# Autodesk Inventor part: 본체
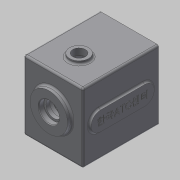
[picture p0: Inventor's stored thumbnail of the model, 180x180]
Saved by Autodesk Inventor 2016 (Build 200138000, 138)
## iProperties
Created: 2016-02
Part Number: 본체
Material: 일반
Document SubType Name: Modeling
Designer: mduedu
Density: 2.71 g/cm^3
Appearance: 기본값
Author: mduedu
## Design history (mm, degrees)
sketch "스케치1"
  geometry: L1 (-47, -47)-(47, -47); L2 (47, -47)-(47, 63); L3 (47, 63)-(-47, 63); L4 (-47, 63)-(-47, -47); 2 further points
  constraints: 8 end point, 2 parallel, 1 horizontal, 1 midpoint, 1 perpendicular, 1 vertical alignment
  dimensions: "d0" = 94 distance of L2.end L3.end; "d155" = 110 distance of L1.end L2.end; "d156" = 47 distance from line of L1 point (0, 0)
extrude "돌출1" new body sketch "스케치1" distance "d2" = 120; taper "d3" = 0 deg
sketch "스케치3"
  geometry: L1 (47, -47)-(-47, -47) reference; L2 (47, 63)-(47, -47) reference; L3 (-47, 63)-(47, 63) reference; L4 (-47, -47)-(-47, 63) reference; L5 (37, 53)-(37, -37); L6 (37, -37)-(-37, -37); L7 (-37, -37)-(-37, 53); L8 (-37, 53)-(37, 53); 1 further point
  constraints: 8 end point, 3 other
  dimensions: "d226" = 10 distance between parallel lines of L8 L3
extrude "돌출3" cut sketch "스케치3" distance "d11" = 110; taper "d12" = 0 deg
sketch "스케치4"
  geometry: C1 r 21 at (0, 11); 1 further point
  constraints: 1 centre point, 1 vertical alignment
  dimensions: "d13" = 21 radius of C1; "d227" = 11 distance of point (0, 0) C1.centre
extrude "돌출4" join sketch "스케치4" distance "d16" = 7; taper "d17" = 0 deg
sketch "스케치5"
  geometry: C1 r 15 at (0, -20); 1 further point
  constraints: 1 centre point, 1 vertical alignment
  dimensions: "d18" = 15 radius of C1; "d20" = 20 distance of point (0, 0) C1.centre
extrude "돌출5" join sketch "스케치5" distance "d21" = 7; taper "d22" = 0 deg
sketch "스케치6"
  geometry: C1 r 30 at (0, 11); A1 r 21 centre (0, 11) between (8.978, -7.984) and (-8.978, -7.984) reference; 1 further point
  constraints: 1 centre point, 1 coincident
  dimensions: "d228" = 60 diameter of C1
extrude "돌출6" join sketch "스케치6" distance "d25" = 7; taper "d26" = -3 deg
hole "구멍1" diameter "d29" = 35; stored, may be unused: countersink angle "d33" = 90 deg, drill point angle "d35" = 0 deg; dims "d27" = 10, "d28" = 10, "d30" = 6, "d31" = 4, "d32" = 2, "d34" = 10
hole "구멍2" diameter "d38" = 22; stored, may be unused: countersink angle "d42" = 90 deg, drill point angle "d44" = 0 deg; dims "d36" = 10, "d37" = 10, "d39" = 6, "d40" = 4, "d41" = 2, "d43" = 7
hole "구멍3" diameter "d47" = 19; stored, may be unused: countersink angle "d51" = 90 deg, drill point angle "d53" = 0 deg; dims "d45" = 10, "d46" = 10, "d48" = 6, "d49" = 4, "d50" = 2, "d52" = 1
hole "구멍4" diameter "d56" = 32; stored, may be unused: countersink angle "d60" = 90 deg, drill point angle "d62" = 0 deg; dims "d57" = 6, "d58" = 4, "d59" = 2, "d61" = 8, "d220" = 10, "d221" = 10
hole "구멍5" diameter "d65" = 25; stored, may be unused: countersink angle "d69" = 90 deg, drill point angle "d71" = 0 deg; dims "d63" = 10, "d64" = 10, "d66" = 6, "d67" = 4, "d68" = 2, "d70" = 8
fillet "모깎기2" dims "d73" = 0.3
fillet "모깎기3" dims "d74" = 2
chamfer "모따기1" distance "d75" = 1; stored, may be unused: second distance "d76" = 2, angle "d77" = 45 deg
fillet "모깎기4" dims "d78" = 3
fillet "모깎기23" dims "d240" = 1
fillet "모깎기20" dims "d229" = 3
sketch "스케치23"
  geometry: L1 (-37, 53)-(37, 53) reference; L2 (37, 53)-(37, -37) reference; L3 (37, -37)-(-37, -37) reference; L4 (-37, -37)-(-37, 53) reference; L5 (44, -47)-(-44, -47) reference; L6 (47, 60)-(47, -44) reference; L7 (-44, 63)-(44, 63) reference; L8 (-47, -44)-(-47, 60) reference; C1 r 10 at (-37, 53); C2 r 10 at (37, 53); C3 r 10 at (-37, -37); C4 r 10 at (37, -37); A1 r 3 centre (-44, -44) between (-47, -44) and (-44, -47) reference; A2 r 3 centre (44, -44) between (44, -47) and (47, -44) reference; A3 r 3 centre (44, 60) between (47, 60) and (44, 63) reference; A4 r 3 centre (-44, 60) between (-44, 63) and (-47, 60) reference; 1 further point
  constraints: 4 centre point, 4 coincident, 3 equal radius
  dimensions: "d230" = 20 diameter of C1
extrude "돌출22" join sketch "스케치23" stored distance "d235" = 10; taper "d236" = 0 deg
fillet "모깎기21" dims "d237" = 3
node "작업 평면1"
fillet "모깎기22" dims "d239" = 1
sketch "스케치12"
  geometry: A1 r 10 centre (-37, 53) between (-34.692, 43.27) and (-27.27, 50.692) reference; A2 r 10 centre (37, 53) between (27.27, 50.692) and (34.692, 43.27) reference; A3 r 10 centre (37, -37) between (34.692, -27.27) and (27.27, -34.692) reference; A4 r 10 centre (-37, -37) between (-27.27, -34.692) and (-34.692, -27.27) reference; 5 further points
  constraints: 4 coincident
hole "구멍6" sketch "스케치12" at (-37, 53), (37, 53), (37, -37), (-37, -37) diameter "d122" = 3.242; stored, may be unused: countersink angle "d126" = 90 deg, drill point angle "d128" = 120 deg; dims "d123" = 7, "d124" = 4, "d125" = 2, "d127" = 9
sketch "스케치20"
  geometry: L1 (44, 0)-(-44, 0) reference; L2 (44, -120)-(-44, -120) reference; L3 (0, 0)-(0, -120); L4 (-44, -120)-(-44, 0) reference; L5 (44, 0)-(44, -120) reference; C1 r 10 at (0, -79)
  constraints: 2 end point, 1 centre point, 1 midpoint, 1 point on line
  dimensions: "d189" = 20 diameter of C1; "d190" = 41 distance from line of C1.centre L2
extrude "돌출19" cut sketch "스케치20" stored distance "d191" = 10; taper "d192" = 0 deg
sketch "스케치18"
  geometry: C1 r 15 at (0, -79); C2 r 10 at (0, -79) reference; 1 further point
  constraints: 1 centre point, 1 concentric
  dimensions: "d174" = 30 diameter of C1
extrude "돌출17" join sketch "스케치18" distance "d175" = 5; taper "d176" = 0 deg
fillet "모깎기16" dims "d177" = 3
sketch "스케치19"
  geometry: C1 r 15 at (24.351, 79); C2 r 10 at (24.351, 79) reference; 1 further point
  constraints: 1 centre point, 1 concentric
  dimensions: "d178" = 30 diameter of C1
extrude "돌출18" cut sketch "스케치19" distance "d181" = 5; taper "d182" = 0 deg
chamfer "모따기5" distance "d183" = 1; stored, may be unused: second distance "d184" = 2, angle "d185" = 45 deg
fillet "모깎기24" dims "d242" = 3, "d243" = 3
sketch "스케치24"
  geometry: L1 (-95, 67)-(-25, 67); L2 (-25, 67)-(-25, 37); L3 (-25, 37)-(-95, 37); L4 (-95, 37)-(-95, 67); L5 (0, 0)-(0, 104) reference; L6 (-95, 52)-(-25, 52); L7 (-60, 67)-(-60, 37); A1 r 15 centre (-95, 52) between (-95, 37) and (-95, 67); A2 r 15 centre (-25, 52) between (-25, 67) and (-25, 37); A3 r 15 centre (-25, 52) between (-25, 37) and (-25, 67); A4 r 15 centre (-95, 52) between (-95, 67) and (-95, 37); 2 further points
  constraints: 12 end point, 8 point on circle, 5 midpoint, 4 centre point, 2 parallel, 2 perpendicular, 1 horizontal, 1 horizontal alignment
  dimensions: "d244" = 60 distance between parallel lines of L7 L5; "d245" = 100 dimension on A2 A1; "d246" = 30 distance between parallel lines of L3 L1
extrude "돌출23" join sketch "스케치24" distance "d247" = 3; taper "d248" = 0 deg
fillet "모깎기25" dims "d249" = 3
sketch "스케치25"
  geometry: L1 (-25, 67)-(-95, 67) reference; L2 (-95, 37)-(-25, 37) reference; A1 r 15 centre (-95, 52) between (-95, 67) and (-95, 37) reference; A2 r 15 centre (-25, 52) between (-25, 37) and (-25, 67) reference; 3 further points
  constraints: 1 horizontal alignment, 1 midpoint, 1 vertical alignment, 1 other
feature "엠보싱3" sketch "스케치25" dims "d250" = 0.5, "d251" = 0
sketch "스케치26"
  geometry: L1 (14.367, 127)-(73.633, 127) reference; L2 (0, 0)-(88, 0) reference; L3 (88, 120)-(0, 120) reference; 5 further points
  constraints: 3 vertical alignment, 2 midpoint
  dimensions: "d252" = 35 distance from line of point (44, 35) L2; "d253" = 35 distance from line of point (44, 85) L3; "d254" = 50 distance of point (44, 35) point (44, 85) (derived)
hole "구멍8" sketch "스케치26" at (44, 85), (44, 35) diameter "d255" = 6.647; stored, may be unused: countersink angle "d259" = 90 deg, drill point angle "d261" = 118 deg; dims "d256" = 6, "d257" = 4, "d258" = 2, "d260" = 8
node "솔리드1"
node "투영된 루프1"
node "투영된 루프4"
node "투영된 루프5"
node "투영된 루프6"
